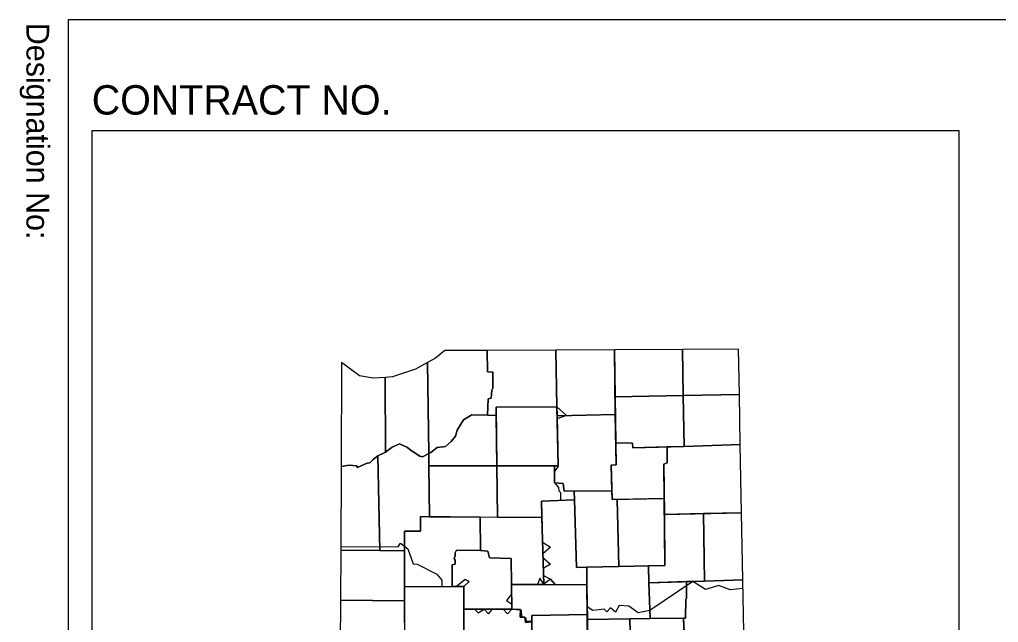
# Model space of a CAD drawing. Extents: x 0.02 to 1.09, y -0.09 to 0.68.
# Drawn here: x 0.0209 to 0.2701, y 0.5256 to 0.6792 of the extents above; entities that cross this region are included whole.
import ezdxf

# ---------------------------------------------------------------- set-up
doc = ezdxf.new("R2010")
doc.units = 0
doc.layers.add('BD_SHT', color=7, linetype='Continuous')
doc.layers.add('BD_SHT_Text', color=7, linetype='Continuous')

msp = doc.modelspace()

# ---------------------------------------------------------------- linework, layer by layer
at = {"layer": 'BD_SHT'}
for p, q in [((0.12912, 0.59484), (0.12675, 0.59287)), ((0.13991, 0.59488), (0.12912, 0.59484)), ((0.1574, 0.59496), (0.13991, 0.59488)), ((0.13997, 0.58939), (0.13991, 0.59488)), ((0.13991, 0.59488), (0.13997, 0.58939)), ((0.17232, 0.59502), (0.1574, 0.59496)), ((0.1574, 0.59496), (0.15768, 0.58048)), ((0.15768, 0.58048), (0.1574, 0.59496)), ((0.1574, 0.59496), (0.15768, 0.58048)), ((0.18966, 0.5951), (0.17232, 0.59502)), ((0.17256, 0.57855), (0.17232, 0.59502)), ((0.17232, 0.59502), (0.1725, 0.58304)), ((0.20396, 0.59516), (0.18966, 0.5951)), ((0.18987, 0.58336), (0.18966, 0.5951)), ((0.18966, 0.5951), (0.18987, 0.58336)), ((0.20417, 0.58362), (0.20396, 0.59516)), ((0.10287, 0.59182), (0.10274, 0.56534)), ((0.10743, 0.58842), (0.10287, 0.59182)), ((0.12477, 0.5918), (0.12169, 0.59014)), ((0.12675, 0.59287), (0.12477, 0.5918)), ((0.12504, 0.56858), (0.12477, 0.5918)), ((0.12477, 0.5918), (0.12504, 0.56858)), ((0.11091, 0.58777), (0.10743, 0.58842)), ((0.12169, 0.59014), (0.11579, 0.58816)), ((0.1414, 0.58932), (0.13997, 0.58939)), ((0.13997, 0.58939), (0.1414, 0.58932)), ((0.14141, 0.58523), (0.1414, 0.58932)), ((0.1414, 0.58932), (0.14141, 0.58523)), ((0.11393, 0.58801), (0.11091, 0.58777)), ((0.11579, 0.58816), (0.11393, 0.58801)), ((0.11401, 0.56895), (0.11393, 0.58801)), ((0.11393, 0.58801), (0.11401, 0.56895)), ((0.14096, 0.58268), (0.14111, 0.58471)), ((0.14111, 0.58471), (0.14096, 0.58268)), ((0.14111, 0.58471), (0.14141, 0.58523)), ((0.14141, 0.58523), (0.14111, 0.58471)), ((0.1725, 0.58304), (0.18987, 0.58336)), ((0.18987, 0.58336), (0.1725, 0.58304)), ((0.18987, 0.58336), (0.20417, 0.58362)), ((0.20417, 0.58362), (0.18987, 0.58336)), ((0.18987, 0.58336), (0.19011, 0.57039)), ((0.19011, 0.57039), (0.18987, 0.58336)), ((0.20439, 0.57092), (0.20417, 0.58362)), ((0.14005, 0.57838), (0.14014, 0.58252)), ((0.14014, 0.58252), (0.14005, 0.57838)), ((0.14014, 0.58252), (0.14096, 0.58268)), ((0.14096, 0.58268), (0.14014, 0.58252)), ((0.1725, 0.58304), (0.17267, 0.57136)), ((0.1339, 0.57719), (0.13606, 0.57844)), ((0.13606, 0.57844), (0.1339, 0.57719)), ((0.13606, 0.57844), (0.14005, 0.57838)), ((0.14005, 0.57838), (0.13606, 0.57844)), ((0.14005, 0.57838), (0.14226, 0.57826)), ((0.14226, 0.57826), (0.14005, 0.57838)), ((0.14224, 0.58041), (0.15768, 0.58048)), ((0.15768, 0.58048), (0.14224, 0.58041)), ((0.14226, 0.57826), (0.14224, 0.58041)), ((0.14224, 0.58041), (0.1424, 0.56546)), ((0.15768, 0.58048), (0.16014, 0.57829)), ((0.15768, 0.58048), (0.15773, 0.57823)), ((0.15798, 0.56544), (0.15768, 0.58048)), ((0.15773, 0.57823), (0.17256, 0.57855)), ((0.17256, 0.57855), (0.15773, 0.57823)), ((0.16014, 0.57829), (0.15774, 0.57745)), ((0.17275, 0.56572), (0.17256, 0.57855)), ((0.13233, 0.57455), (0.1339, 0.57719)), ((0.1339, 0.57719), (0.13233, 0.57455)), ((0.1424, 0.56546), (0.14226, 0.57826)), ((0.15773, 0.57823), (0.15798, 0.56544)), ((0.15774, 0.57745), (0.15798, 0.56539)), ((0.13189, 0.57301), (0.13233, 0.57455)), ((0.13233, 0.57455), (0.13189, 0.57301)), ((0.11571, 0.57024), (0.11757, 0.57111)), ((0.11757, 0.57111), (0.11571, 0.57024)), ((0.11757, 0.57111), (0.11948, 0.57027)), ((0.11948, 0.57027), (0.11757, 0.57111)), ((0.12935, 0.57041), (0.13079, 0.57168)), ((0.13079, 0.57168), (0.12935, 0.57041)), ((0.13079, 0.57168), (0.13189, 0.57301)), ((0.13189, 0.57301), (0.13079, 0.57168)), ((0.17267, 0.57136), (0.17696, 0.57122)), ((0.17696, 0.57122), (0.17267, 0.57136)), ((0.17267, 0.57136), (0.17275, 0.56571)), ((0.17696, 0.57122), (0.17699, 0.57007)), ((0.17699, 0.57007), (0.17696, 0.57122)), ((0.19011, 0.57039), (0.20439, 0.57092)), ((0.20439, 0.57092), (0.19011, 0.57039)), ((0.20471, 0.55354), (0.20439, 0.57092)), ((0.11208, 0.568), (0.11401, 0.56895)), ((0.11401, 0.56895), (0.11208, 0.568)), ((0.11401, 0.56895), (0.11571, 0.57024)), ((0.11571, 0.57024), (0.11401, 0.56895)), ((0.11948, 0.57027), (0.12086, 0.56922)), ((0.12086, 0.56922), (0.11948, 0.57027)), ((0.12086, 0.56922), (0.12279, 0.56796)), ((0.12279, 0.56796), (0.12086, 0.56922)), ((0.12347, 0.56778), (0.12504, 0.56858)), ((0.12504, 0.56858), (0.12347, 0.56778)), ((0.12504, 0.56858), (0.12561, 0.56887)), ((0.12561, 0.56887), (0.12504, 0.56858)), ((0.12504, 0.56858), (0.12508, 0.56548)), ((0.12508, 0.56548), (0.12504, 0.56858)), ((0.12561, 0.56887), (0.12723, 0.57014)), ((0.12723, 0.57014), (0.12561, 0.56887)), ((0.12723, 0.57014), (0.12935, 0.57041)), ((0.12935, 0.57041), (0.12723, 0.57014)), ((0.17699, 0.57007), (0.19011, 0.57039)), ((0.18573, 0.57029), (0.17699, 0.57007)), ((0.19011, 0.57039), (0.18573, 0.57029)), ((0.18573, 0.57029), (0.18579, 0.56621)), ((0.18579, 0.56621), (0.18573, 0.57029)), ((0.108, 0.56554), (0.10937, 0.56612)), ((0.10937, 0.56612), (0.108, 0.56554)), ((0.10937, 0.56612), (0.11001, 0.56623)), ((0.11001, 0.56623), (0.10937, 0.56612)), ((0.11001, 0.56623), (0.11094, 0.56708)), ((0.11094, 0.56708), (0.11001, 0.56623)), ((0.11094, 0.56708), (0.11208, 0.568)), ((0.11208, 0.568), (0.11094, 0.56708)), ((0.11257, 0.54394), (0.11208, 0.568)), ((0.11208, 0.568), (0.11257, 0.54394)), ((0.12279, 0.56796), (0.12347, 0.56778)), ((0.12347, 0.56778), (0.12279, 0.56796)), ((0.18579, 0.56621), (0.18494, 0.56593)), ((0.18494, 0.56593), (0.18579, 0.56621)), ((0.18494, 0.56593), (0.18507, 0.55311)), ((0.18503, 0.55715), (0.18494, 0.56593)), ((0.10274, 0.56534), (0.10263, 0.54397)), ((0.10274, 0.56534), (0.10479, 0.56568)), ((0.10479, 0.56568), (0.10274, 0.56534)), ((0.10479, 0.56568), (0.10663, 0.56545)), ((0.10663, 0.56545), (0.10479, 0.56568)), ((0.10663, 0.56545), (0.10691, 0.56506)), ((0.10691, 0.56506), (0.10663, 0.56545)), ((0.10691, 0.56506), (0.108, 0.56554)), ((0.108, 0.56554), (0.10691, 0.56506)), ((0.12508, 0.56548), (0.1424, 0.56546)), ((0.1424, 0.56546), (0.12508, 0.56548)), ((0.12508, 0.56548), (0.12523, 0.55251)), ((0.12523, 0.55251), (0.12508, 0.56548)), ((0.1424, 0.56546), (0.15798, 0.56544)), ((0.14254, 0.55237), (0.1424, 0.56546)), ((0.15704, 0.56545), (0.1424, 0.56546)), ((0.1424, 0.56546), (0.1424, 0.56546)), ((0.1424, 0.56546), (0.14254, 0.55237)), ((0.15798, 0.56544), (0.15704, 0.56545)), ((0.15704, 0.56545), (0.15707, 0.56117)), ((0.15707, 0.56117), (0.15704, 0.56545)), ((0.15798, 0.56539), (0.15705, 0.56406)), ((0.15705, 0.56406), (0.15707, 0.56117)), ((0.17154, 0.56566), (0.17275, 0.56571)), ((0.17275, 0.56571), (0.17154, 0.56566)), ((0.17171, 0.55913), (0.17154, 0.56566)), ((0.17154, 0.56566), (0.17177, 0.55689)), ((0.17275, 0.56571), (0.17275, 0.56572)), ((0.15707, 0.56117), (0.15808, 0.55994)), ((0.15707, 0.56117), (0.15924, 0.56097)), ((0.15924, 0.56097), (0.15707, 0.56117)), ((0.15924, 0.56097), (0.1595, 0.55901)), ((0.1595, 0.55901), (0.15924, 0.56097)), ((0.15808, 0.55994), (0.15819, 0.5591)), ((0.15819, 0.5591), (0.15859, 0.55871)), ((0.15859, 0.55871), (0.15863, 0.55668)), ((0.1595, 0.55901), (0.17171, 0.55913)), ((0.16206, 0.55904), (0.1595, 0.55901)), ((0.17171, 0.55913), (0.16206, 0.55904)), ((0.16214, 0.55682), (0.16206, 0.55904)), ((0.16206, 0.55904), (0.16214, 0.55682)), ((0.17177, 0.55689), (0.17171, 0.55913)), ((0.15373, 0.55649), (0.16214, 0.55682)), ((0.16214, 0.55682), (0.15373, 0.55649)), ((0.15863, 0.55668), (0.15373, 0.55649)), ((0.15373, 0.55649), (0.15402, 0.54604)), ((0.15385, 0.55227), (0.15373, 0.55649)), ((0.15373, 0.55649), (0.15385, 0.55227)), ((0.16271, 0.53957), (0.16214, 0.55682)), ((0.16214, 0.55682), (0.16271, 0.53957)), ((0.17177, 0.55689), (0.18503, 0.55715)), ((0.173, 0.55692), (0.17177, 0.55689)), ((0.18503, 0.55715), (0.173, 0.55692)), ((0.17347, 0.53981), (0.173, 0.55692)), ((0.173, 0.55692), (0.17347, 0.53981)), ((0.1852, 0.54007), (0.18503, 0.55715)), ((0.18507, 0.55311), (0.20471, 0.55354)), ((0.20471, 0.55354), (0.19499, 0.55332)), ((0.20501, 0.53639), (0.20471, 0.55354)), ((0.12292, 0.54881), (0.12298, 0.55253)), ((0.12298, 0.55253), (0.12292, 0.54881)), ((0.12298, 0.55253), (0.12523, 0.55251)), ((0.13812, 0.5524), (0.12298, 0.55253)), ((0.12523, 0.55251), (0.14254, 0.55237)), ((0.15385, 0.55227), (0.13812, 0.5524)), ((0.13812, 0.5524), (0.13819, 0.54394)), ((0.13819, 0.54394), (0.13812, 0.5524)), ((0.14254, 0.55237), (0.15385, 0.55227)), ((0.15432, 0.53526), (0.15385, 0.55227)), ((0.15385, 0.55227), (0.15432, 0.53526)), ((0.19499, 0.55332), (0.18507, 0.55311)), ((0.18507, 0.55311), (0.1852, 0.54007)), ((0.19527, 0.5361), (0.19499, 0.55332)), ((0.19499, 0.55332), (0.19527, 0.5361)), ((0.11887, 0.54382), (0.11887, 0.54883)), ((0.11887, 0.54883), (0.12292, 0.54881)), ((0.12292, 0.54881), (0.11887, 0.54883)), ((0.11887, 0.54883), (0.11887, 0.54382)), ((0.15402, 0.54604), (0.15605, 0.54473)), ((0.10263, 0.54397), (0.10256, 0.53121)), ((0.10263, 0.54495), (0.1173, 0.5448)), ((0.10263, 0.54397), (0.11257, 0.54394)), ((0.11257, 0.54394), (0.10263, 0.54397)), ((0.11887, 0.54382), (0.11257, 0.54394)), ((0.11257, 0.54394), (0.11887, 0.54382)), ((0.1173, 0.5448), (0.11783, 0.54579)), ((0.11783, 0.54579), (0.1197, 0.54433)), ((0.11888, 0.53531), (0.11887, 0.54382)), ((0.11887, 0.54382), (0.11888, 0.53531)), ((0.1197, 0.54433), (0.12112, 0.54049)), ((0.13174, 0.5433), (0.13215, 0.54398)), ((0.13215, 0.54398), (0.13174, 0.5433)), ((0.13215, 0.54398), (0.13819, 0.54394)), ((0.13819, 0.54394), (0.13215, 0.54398)), ((0.13819, 0.54394), (0.14013, 0.54375)), ((0.14013, 0.54375), (0.13819, 0.54394)), ((0.14013, 0.54375), (0.14051, 0.54207)), ((0.14051, 0.54207), (0.14013, 0.54375)), ((0.15605, 0.54473), (0.1541, 0.54304)), ((0.13153, 0.54186), (0.1318, 0.54258)), ((0.1318, 0.54258), (0.13153, 0.54186)), ((0.13174, 0.54145), (0.13153, 0.54186)), ((0.13153, 0.54186), (0.13174, 0.54145)), ((0.1318, 0.54258), (0.13174, 0.5433)), ((0.13174, 0.5433), (0.1318, 0.54258)), ((0.13178, 0.54103), (0.13174, 0.54145)), ((0.13174, 0.54145), (0.13178, 0.54103)), ((0.13181, 0.54043), (0.13178, 0.54103)), ((0.13178, 0.54103), (0.13181, 0.54043)), ((0.14051, 0.54207), (0.14605, 0.54185)), ((0.14605, 0.54185), (0.14051, 0.54207)), ((0.14605, 0.54185), (0.14611, 0.53526)), ((0.14617, 0.52893), (0.14605, 0.54185)), ((0.1541, 0.54304), (0.15413, 0.54208)), ((0.15413, 0.54208), (0.15604, 0.54038)), ((0.12112, 0.54049), (0.12212, 0.54039)), ((0.12212, 0.54039), (0.12715, 0.5379)), ((0.13099, 0.54022), (0.13181, 0.54043)), ((0.13181, 0.54043), (0.13099, 0.54022)), ((0.13099, 0.53471), (0.13099, 0.54022)), ((0.13099, 0.54022), (0.13099, 0.53471)), ((0.15604, 0.54038), (0.15421, 0.53936)), ((0.15421, 0.53936), (0.15426, 0.53756)), ((0.16529, 0.53962), (0.16271, 0.53957)), ((0.16271, 0.53957), (0.16529, 0.53962)), ((0.16529, 0.53962), (0.17347, 0.53981)), ((0.17347, 0.53981), (0.16529, 0.53962)), ((0.16534, 0.53512), (0.16529, 0.53962)), ((0.16529, 0.53962), (0.16534, 0.53512)), ((0.17347, 0.53981), (0.1852, 0.54007)), ((0.18102, 0.53998), (0.17347, 0.53981)), ((0.1852, 0.54007), (0.18102, 0.53998)), ((0.18102, 0.53998), (0.18112, 0.53569)), ((0.18112, 0.53569), (0.18102, 0.53998)), ((0.12715, 0.5379), (0.12838, 0.53631)), ((0.12838, 0.53631), (0.12841, 0.5347)), ((0.1321, 0.5348), (0.13434, 0.53664)), ((0.13535, 0.536), (0.13397, 0.53472)), ((0.13434, 0.53664), (0.13535, 0.536)), ((0.15333, 0.53685), (0.15276, 0.53526)), ((0.15432, 0.53533), (0.15333, 0.53685)), ((0.15426, 0.53756), (0.15608, 0.5366)), ((0.15608, 0.5366), (0.15432, 0.53533)), ((0.15727, 0.53523), (0.15608, 0.5366)), ((0.15608, 0.5366), (0.15727, 0.53523)), ((0.18112, 0.53569), (0.19527, 0.5361)), ((0.19065, 0.53597), (0.18112, 0.53569)), ((0.19233, 0.53602), (0.18136, 0.5286)), ((0.19527, 0.5361), (0.19065, 0.53597)), ((0.19065, 0.53597), (0.19068, 0.53169)), ((0.19068, 0.53169), (0.19065, 0.53597)), ((0.19556, 0.53397), (0.19233, 0.53602)), ((0.19527, 0.5361), (0.20501, 0.53639)), ((0.20501, 0.53639), (0.19527, 0.5361)), ((0.20525, 0.52319), (0.20501, 0.53639)), ((0.11889, 0.53107), (0.11888, 0.53531)), ((0.11888, 0.53531), (0.11888, 0.53467)), ((0.13099, 0.53471), (0.11888, 0.53467)), ((0.11888, 0.53467), (0.13099, 0.53471)), ((0.11888, 0.53467), (0.1189, 0.51843)), ((0.12841, 0.5347), (0.1321, 0.5348)), ((0.13397, 0.53472), (0.13099, 0.53471)), ((0.13099, 0.53471), (0.13397, 0.53472)), ((0.13397, 0.53472), (0.13397, 0.52898)), ((0.13397, 0.51843), (0.13397, 0.53472)), ((0.13397, 0.53472), (0.13397, 0.52898)), ((0.15276, 0.53526), (0.14611, 0.53526)), ((0.14611, 0.53526), (0.14613, 0.53278)), ((0.14611, 0.53526), (0.15432, 0.53526)), ((0.15432, 0.53526), (0.14611, 0.53526)), ((0.14611, 0.53526), (0.14617, 0.52893)), ((0.15432, 0.53526), (0.16534, 0.53512)), ((0.16534, 0.53512), (0.15432, 0.53526)), ((0.16534, 0.53512), (0.15727, 0.53523)), ((0.1654, 0.52959), (0.16534, 0.53512)), ((0.16534, 0.53512), (0.16544, 0.52631)), ((0.16543, 0.5276), (0.16534, 0.53512)), ((0.16534, 0.53512), (0.16534, 0.53512)), ((0.18112, 0.53569), (0.18142, 0.52654)), ((0.18142, 0.52654), (0.18112, 0.53569)), ((0.1989, 0.53497), (0.19556, 0.53397)), ((0.20184, 0.53391), (0.1989, 0.53497)), ((0.20505, 0.53424), (0.20184, 0.53391)), ((0.10256, 0.53121), (0.10248, 0.51494)), ((0.10256, 0.53121), (0.11889, 0.53107)), ((0.11889, 0.53107), (0.10256, 0.53121)), ((0.11889, 0.52557), (0.11889, 0.53107)), ((0.14613, 0.53278), (0.14483, 0.5312)), ((0.14483, 0.5312), (0.14615, 0.53035)), ((0.19054, 0.53153), (0.19045, 0.52667)), ((0.19045, 0.52667), (0.19054, 0.53153)), ((0.19068, 0.53169), (0.19054, 0.53153)), ((0.19054, 0.53153), (0.19068, 0.53169)), ((0.13397, 0.52898), (0.13672, 0.52897)), ((0.13397, 0.52898), (0.14617, 0.52893)), ((0.14617, 0.52893), (0.13397, 0.52898)), ((0.13397, 0.52898), (0.13397, 0.52898)), ((0.13397, 0.52898), (0.13397, 0.51656)), ((0.13672, 0.52897), (0.13763, 0.52802)), ((0.13763, 0.52802), (0.13915, 0.52896)), ((0.13915, 0.52896), (0.1403, 0.52779)), ((0.1403, 0.52779), (0.14129, 0.52895)), ((0.14129, 0.52895), (0.14398, 0.52894)), ((0.14398, 0.52894), (0.14507, 0.52776)), ((0.14507, 0.52776), (0.14617, 0.52893)), ((0.14615, 0.53035), (0.14617, 0.52893)), ((0.14617, 0.52893), (0.14859, 0.52878)), ((0.14617, 0.52893), (0.14859, 0.52878)), ((0.14617, 0.52893), (0.14845, 0.52887)), ((0.14845, 0.52887), (0.14617, 0.52893)), ((0.14845, 0.52887), (0.14835, 0.5269)), ((0.14835, 0.5269), (0.14845, 0.52887)), ((0.14859, 0.52878), (0.14865, 0.52691)), ((0.16686, 0.52864), (0.1654, 0.52959)), ((0.16969, 0.52893), (0.16686, 0.52864)), ((0.17039, 0.52829), (0.16969, 0.52893)), ((0.17134, 0.52928), (0.17039, 0.52829)), ((0.17261, 0.52823), (0.17134, 0.52928)), ((0.17358, 0.52986), (0.17261, 0.52823)), ((0.17602, 0.52973), (0.17358, 0.52986)), ((0.17837, 0.528), (0.17602, 0.52973)), ((0.18136, 0.5286), (0.17837, 0.528)), ((0.14835, 0.5269), (0.14951, 0.5269)), ((0.14951, 0.5269), (0.14835, 0.5269)), ((0.14865, 0.52691), (0.14965, 0.52681)), ((0.14951, 0.5269), (0.1497, 0.52559)), ((0.1497, 0.52559), (0.14951, 0.5269)), ((0.14965, 0.52681), (0.14986, 0.52597)), ((0.14986, 0.52597), (0.15132, 0.52586)), ((0.1513, 0.52737), (0.16543, 0.5276)), ((0.16543, 0.5276), (0.1513, 0.52737)), ((0.15132, 0.5257), (0.1513, 0.52737)), ((0.1513, 0.52737), (0.15132, 0.5257)), ((0.16553, 0.51832), (0.16543, 0.5276)), ((0.16544, 0.52631), (0.18142, 0.52654)), ((0.17626, 0.52647), (0.16544, 0.52631)), ((0.16544, 0.52631), (0.16568, 0.50476)), ((0.18142, 0.52654), (0.17626, 0.52647)), ((0.1767, 0.5048), (0.17626, 0.52647)), ((0.17626, 0.52647), (0.17657, 0.51133)), ((0.18142, 0.52654), (0.19045, 0.52667)), ((0.18995, 0.52666), (0.18142, 0.52654)), ((0.19045, 0.52667), (0.18995, 0.52666)), ((0.18995, 0.52666), (0.19007, 0.52298)), ((0.19044, 0.51165), (0.18995, 0.52666)), ((0.1497, 0.52559), (0.15132, 0.5257)), ((0.15066, 0.52565), (0.1497, 0.52559)), ((0.15132, 0.5257), (0.15066, 0.52565)), ((0.15132, 0.52586), (0.15151, 0.50395)), ((0.15132, 0.5257), (0.15138, 0.51853)), ((0.1514, 0.51622), (0.15132, 0.5257))]:
    msp.add_line(p, q, dxfattribs=at)
msp.add_lwpolyline([(0.03333, 0.02917), (0.03333, 0.67917), (0.88333, 0.67917), (0.88333, 0.02917)], close=True, dxfattribs=at)
msp.add_lwpolyline([(0.03924, 0.33397), (0.26008, 0.33397), (0.26008, 0.65078), (0.03924, 0.65078), (0.03924, 0.33397)], dxfattribs=at)

# ---------------------------------------------------------------- texts
at = {"layer": 'BD_SHT_Text'}
msp.add_text('Designation No:', height=0.0058, rotation=270, dxfattribs=at).set_placement((0.02261, 0.67834))
msp.add_text('CONTRACT NO. ', height=0.0075, dxfattribs=at).set_placement((0.03924, 0.65495))

doc.saveas('drawing.dxf')
